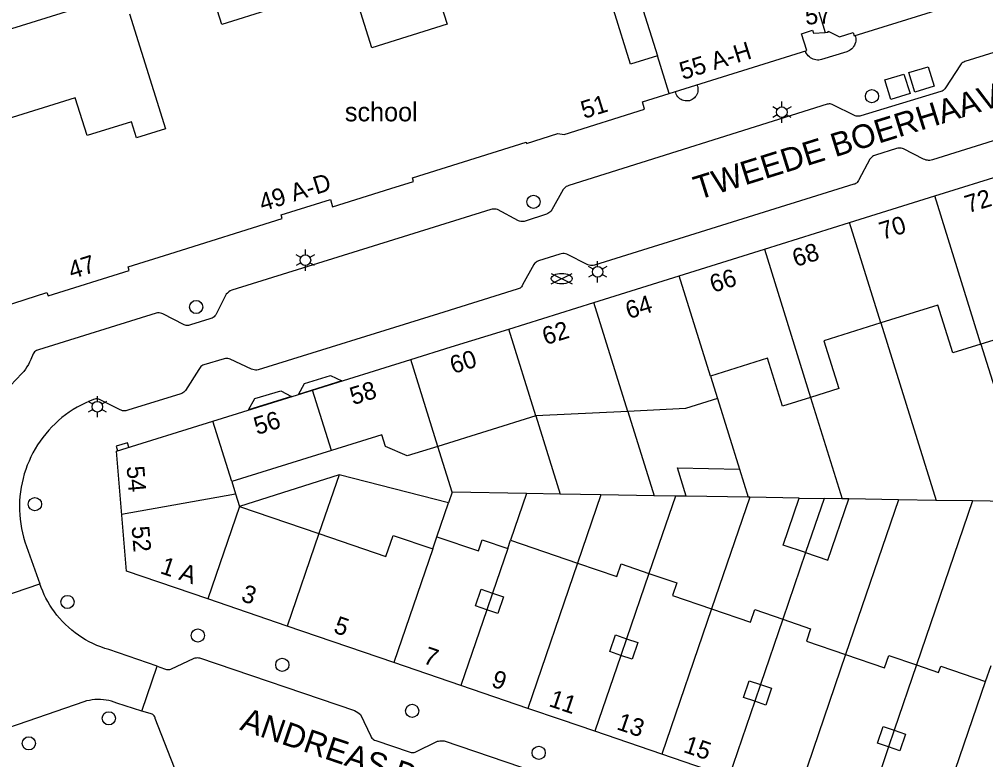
# Model space of a CAD drawing. Extents: x 122462 to 123306, y 485548 to 486417.
# Drawn here: x 122727.9 to 122810, y 485830.6 to 485893.5 of the extents above; entities that cross this region are included whole.
import ezdxf

# ---------------------------------------------------------------- set-up
doc = ezdxf.new("R2010")
doc.units = 0
for name, color, linetype in [('B-WE-IE-MEUBILAIR_WEGMEUBILAIR_VERKEERSBORD-S', 7, 'Continuous'), ('Level 1', 7, 'Continuous'), ('Level 10', 7, 'Continuous'), ('Level 11', 7, 'Continuous'), ('Level 17', 7, 'Continuous'), ('Level 19', 7, 'Continuous'), ('Level 2', 7, 'Continuous'), ('Level 4', 7, 'Continuous'), ('Level 40', 7, 'Continuous'), ('Level 42', 7, 'Continuous'), ('Level 50', 7, 'Continuous'), ('Level 52', 7, 'Continuous'), ('Level 53', 7, 'Continuous'), ('Level 62', 7, 'Continuous'), ('N-WE-AL-T25', 7, 'Continuous'), ('N-WE-GR-BOOM_DOORWORTELBARE RUIMTE-G', 7, 'Continuous')]:
    doc.layers.add(name, color=color, linetype=linetype)

msp = doc.modelspace()

# ---------------------------------------------------------------- linework, layer by layer
at = {"layer": 'Level 1'}
for p, q in [((122805.66, 485878.489), (122812.618, 485880.656)), ((122798.427, 485876.231), (122805.66, 485878.489)), ((122791.193, 485873.971), (122798.427, 485876.231)), ((122783.959, 485871.711), (122791.193, 485873.971)), ((122776.725, 485869.451), (122783.959, 485871.711)), ((122769.489, 485867.189), (122776.725, 485869.451)), ((122752.831, 485862.006), (122761.161, 485864.598)), ((122786.615, 485863.192), (122787.212, 485861.277)), ((122744.368, 485859.372), (122752.831, 485862.006)), ((122771.792, 485859.813), (122763.461, 485857.217)), ((122779.612, 485860.192), (122771.792, 485859.813)), ((122754.431, 485856.87), (122745.968, 485854.233)), ((122745.968, 485854.233), (122746.288, 485853.206)), ((122746.288, 485853.206), (122746.627, 485852.12)), ((122746.627, 485852.12), (122753.368, 485849.816)), ((122763.031, 485848.517), (122763.385, 485849.552)), ((122769.401, 485848.56), (122769.639, 485849.256)), ((122769.639, 485849.256), (122775.329, 485847.311)), ((122750.682, 485841.957), (122743.941, 485844.263)), ((122759.729, 485838.86), (122750.682, 485841.957)), ((122765.421, 485836.916), (122759.729, 485838.86)), ((122809.978, 485837.258), (122810.439, 485838.605)), ((122771.11, 485834.969), (122765.421, 485836.916)), ((122782.494, 485831.088), (122776.809, 485833.029)), ((122788.178, 485829.144), (122782.494, 485831.088))]:
    msp.add_line(p, q, dxfattribs=at)
for points in [[(122782.111, 485890.389), (122779.836, 485889.68), (122776.933, 485898.985), (122779.2, 485899.692), (122778.052, 485903.361), (122777.009, 485903.036)], [(122787.577, 485901.162), (122779.528, 485898.643), (122782.111, 485890.389)], [(122763.191, 485896.451), (122764.246, 485893.07), (122757.854, 485891.075), (122755.209, 485899.548)], [(122749.287, 485894.36), (122745.115, 485893.057), (122744.165, 485896.101)], [(122796.371, 485892.381), (122796.609, 485892.396), (122796.604, 485892.486), (122797.563, 485891.992), (122798.727, 485892.355), (122798.811, 485892.088), (122810.229, 485895.65)], [(122737.289, 485893.955), (122740.339, 485884.181), (122737.882, 485883.414), (122737.452, 485884.79), (122733.686, 485883.614), (122732.684, 485886.823), (122726.415, 485884.866), (122725.594, 485887.497), (122718.359, 485885.239), (122718.533, 485884.68), (122716.39, 485883.999), (122716.428, 485883.886), (122716.294, 485883.843)], [(122783.11, 485887.189), (122794.792, 485890.834), (122794.345, 485892.266), (122795.281, 485892.558), (122795.355, 485892.319), (122796.371, 485892.381)], [(122721.249, 485867.901), (122721.34, 485867.91), (122723.61, 485868.642), (122723.749, 485868.199), (122730.269, 485870.299), (122730.37, 485869.999), (122737.259, 485872.16), (122737.166, 485872.466), (122740.722, 485873.58), (122750.259, 485876.569), (122750.165, 485876.879), (122754.35, 485878.189), (122754.529, 485877.559), (122759.482, 485879.109), (122761.4, 485879.709), (122761.301, 485880.031), (122770.958, 485883.053), (122770.989, 485882.949), (122773.66, 485883.789), (122774.189, 485883.709), (122781.029, 485885.85), (122780.835, 485886.479), (122783.11, 485887.189)], [(122815.276, 485872.131), (122810.708, 485870.706), (122811.975, 485866.643), (122809.588, 485865.899)], [(122809.588, 485865.899), (122807.202, 485865.155), (122805.935, 485869.217), (122801.086, 485867.705)], [(122761.161, 485864.598), (122764.611, 485865.671), (122769.489, 485867.189)], [(122801.086, 485867.705), (122796.238, 485866.193), (122797.505, 485862.131), (122795.118, 485861.386)], [(122795.118, 485861.386), (122792.732, 485860.642), (122791.465, 485864.704), (122786.615, 485863.192)], [(122787.212, 485861.277), (122784.489, 485860.428), (122779.612, 485860.192)], [(122743.941, 485844.263), (122737.019, 485846.63), (122736.17, 485856.819), (122744.368, 485859.372)], [(122763.461, 485857.217), (122760.861, 485856.407), (122759.027, 485857.214), (122758.718, 485858.206), (122754.431, 485856.87)], [(122753.368, 485849.816), (122759.055, 485847.872), (122759.669, 485849.666), (122763.031, 485848.517)], [(122763.385, 485849.552), (122766.918, 485848.344), (122767.244, 485849.298), (122769.401, 485848.56)], [(122775.329, 485847.311), (122778.663, 485846.172), (122779.028, 485847.24), (122781.393, 485846.432)], [(122781.393, 485846.432), (122783.759, 485845.623), (122783.394, 485844.555), (122786.71, 485843.421)], [(122767.621, 485843.351), (122766.674, 485843.675), (122767.159, 485845.095), (122768.106, 485844.771)], [(122768.106, 485844.771), (122769.052, 485844.448), (122768.567, 485843.028), (122767.621, 485843.351)], [(122786.71, 485843.421), (122790.029, 485842.287), (122790.394, 485843.356), (122792.759, 485842.547)], [(122792.759, 485842.547), (122795.125, 485841.738), (122794.759, 485840.669), (122798.077, 485839.535)], [(122779.011, 485839.466), (122778.065, 485839.79), (122778.551, 485841.21), (122779.497, 485840.887)], [(122779.497, 485840.887), (122780.444, 485840.563), (122779.958, 485839.142), (122779.011, 485839.466)], [(122798.077, 485839.535), (122801.39, 485838.403), (122801.755, 485839.472), (122804.12, 485838.663)], [(122804.12, 485838.663), (122805.994, 485838.023), (122806.177, 485838.558), (122809.978, 485837.258)], [(122790.378, 485835.58), (122789.432, 485835.903), (122789.917, 485837.323), (122790.863, 485837)], [(122790.863, 485837), (122791.809, 485836.676), (122791.324, 485835.256), (122790.378, 485835.58)], [(122776.809, 485833.029), (122773.96, 485833.999), (122771.11, 485834.969)], [(122801.738, 485831.696), (122800.792, 485832.019), (122801.277, 485833.439), (122802.223, 485833.116)], [(122802.223, 485833.116), (122803.17, 485832.792), (122802.685, 485831.372), (122801.738, 485831.696)]]:
    msp.add_lwpolyline(points, dxfattribs=at)
at = {"layer": 'Level 10'}
for points in [[(122751.637, 485861.634), (122752.153, 485862.556), (122754.359, 485863.246), (122755.302, 485862.775), (122751.637, 485861.634)], [(122747.398, 485860.315), (122747.926, 485861.287), (122750.14, 485861.939), (122751.03, 485861.445), (122747.398, 485860.315)]]:
    msp.add_lwpolyline(points, dxfattribs=at)
at = {"layer": 'Level 11'}
for points in [[(122798.91, 485892.119), (122798.94, 485891.999), (122798.957, 485891.877), (122798.96, 485891.753), (122798.949, 485891.63), (122798.925, 485891.509), (122798.887, 485891.392), (122798.836, 485891.279), (122798.772, 485891.173), (122798.697, 485891.075), (122798.612, 485890.985), (122798.517, 485890.906), (122798.414, 485890.838), (122798.304, 485890.782), (122798.188, 485890.739), (122796.059, 485890.075), (122795.939, 485890.045), (122795.817, 485890.028), (122795.693, 485890.026), (122795.57, 485890.037), (122795.449, 485890.062), (122795.332, 485890.1), (122795.219, 485890.151), (122795.113, 485890.215), (122795.015, 485890.29), (122794.926, 485890.375), (122794.847, 485890.47), (122794.779, 485890.573), (122794.723, 485890.683), (122794.68, 485890.799)], [(122785.464, 485887.925), (122785.509, 485887.812), (122785.54, 485887.694), (122785.555, 485887.573), (122785.555, 485887.451), (122785.539, 485887.331), (122785.509, 485887.213), (122785.464, 485887.1), (122785.404, 485886.993), (122785.332, 485886.895), (122785.248, 485886.807), (122785.154, 485886.73), (122785.05, 485886.666), (122784.94, 485886.615), (122784.823, 485886.579), (122784.703, 485886.558), (122784.582, 485886.552), (122784.46, 485886.561), (122784.341, 485886.586), (122784.226, 485886.626), (122784.117, 485886.679), (122784.015, 485886.747), (122783.923, 485886.826), (122783.842, 485886.917), (122783.772, 485887.017), (122783.716, 485887.125), (122783.674, 485887.239), (122783.647, 485887.358)]]:
    msp.add_lwpolyline(points, dxfattribs=at)
at = {"layer": 'Level 17'}
for p, q in [((122726.438, 485844.434), (122729.679, 485845.54)), ((122738.321, 485834.728), (122739.631, 485838.555))]:
    msp.add_line(p, q, dxfattribs=at)
for points in [[(122825.381, 485895.245), (122808.209, 485889.895), (122808.123, 485889.862), (122808.041, 485889.817), (122807.967, 485889.762), (122807.9, 485889.698), (122807.842, 485889.626), (122806.575, 485887.656), (122806.516, 485887.577), (122806.447, 485887.507), (122806.369, 485887.448), (122806.283, 485887.4), (122806.191, 485887.365), (122799.392, 485885.284), (122799.293, 485885.265), (122799.192, 485885.257), (122799.092, 485885.261), (122798.992, 485885.277), (122798.895, 485885.304), (122796.955, 485886.254), (122796.873, 485886.281), (122796.788, 485886.297), (122796.702, 485886.302), (122796.616, 485886.295), (122796.532, 485886.277), (122774.587, 485879.372), (122774.478, 485879.332), (122774.375, 485879.277), (122774.28, 485879.208), (122774.196, 485879.128), (122774.123, 485879.037), (122773.136, 485877.296)], [(122827.346, 485888.392), (122805.468, 485881.555), (122805.362, 485881.528), (122805.253, 485881.513), (122805.143, 485881.51), (122805.034, 485881.519), (122804.926, 485881.54), (122804.822, 485881.572), (122804.721, 485881.616), (122803.006, 485882.477), (122802.912, 485882.512), (122802.814, 485882.535), (122802.714, 485882.547), (122802.614, 485882.546), (122802.514, 485882.535), (122802.416, 485882.511), (122800.644, 485881.961), (122800.549, 485881.927), (122800.458, 485881.882), (122800.373, 485881.827), (122800.295, 485881.763), (122800.224, 485881.691), (122800.162, 485881.611), (122799.223, 485879.869), (122799.189, 485879.788), (122799.142, 485879.712), (122799.085, 485879.644), (122799.019, 485879.586), (122798.945, 485879.538), (122798.864, 485879.502), (122798.779, 485879.478)], [(122798.779, 485879.478), (122776.782, 485872.606), (122776.668, 485872.582), (122776.551, 485872.573), (122776.435, 485872.579), (122776.32, 485872.6), (122776.209, 485872.636), (122774.429, 485873.553), (122774.311, 485873.58), (122774.19, 485873.594), (122774.068, 485873.594), (122773.947, 485873.58), (122773.829, 485873.553), (122772.001, 485872.967), (122771.911, 485872.927), (122771.828, 485872.876), (122771.752, 485872.813), (122771.686, 485872.741), (122771.63, 485872.661), (122770.665, 485870.931), (122770.631, 485870.852), (122770.584, 485870.779), (122770.526, 485870.716), (122770.458, 485870.662), (122770.382, 485870.621), (122770.301, 485870.592), (122770.216, 485870.577), (122763.535, 485868.492), (122748.215, 485863.71), (122748.099, 485863.7), (122747.982, 485863.702), (122747.866, 485863.716), (122747.753, 485863.742), (122747.642, 485863.779), (122745.831, 485864.618), (122745.734, 485864.65), (122745.633, 485864.672), (122745.531, 485864.682), (122745.429, 485864.682), (122745.327, 485864.67), (122743.603, 485864.161), (122743.509, 485864.121), (122743.422, 485864.069), (122743.344, 485864.004), (122743.276, 485863.928), (122743.22, 485863.843), (122743.177, 485863.751), (122742.037, 485861.977), (122741.972, 485861.897), (122741.898, 485861.826), (122741.815, 485861.764), (122741.726, 485861.712), (122741.631, 485861.672), (122737.136, 485860.305), (122737.05, 485860.266), (122736.959, 485860.241), (122736.865, 485860.23), (122736.77, 485860.233), (122736.677, 485860.252), (122736.588, 485860.284), (122736.505, 485860.329), (122734.741, 485861.196), (122734.644, 485861.229), (122734.542, 485861.248), (122734.439, 485861.25), (122734.337, 485861.237), (122734.238, 485861.209), (122733.877, 485861.064), (122733.522, 485860.904), (122733.173, 485860.731), (122732.832, 485860.544), (122732.498, 485860.343), (122732.173, 485860.129), (122731.857, 485859.902), (122731.549, 485859.663), (122731.252, 485859.412), (122730.965, 485859.149), (122730.688, 485858.875), (122730.423, 485858.59), (122730.17, 485858.295), (122729.928, 485857.99), (122729.699, 485857.675), (122729.482, 485857.352), (122729.279, 485857.02), (122729.089, 485856.68), (122728.912, 485856.333), (122728.75, 485855.979), (122728.602, 485855.619), (122728.468, 485855.253), (122728.349, 485854.883), (122728.245, 485854.507), (122728.156, 485854.129), (122728.082, 485853.746), (122728.024, 485853.361), (122727.981, 485852.974), (122727.953, 485852.586), (122727.941, 485852.197), (122727.945, 485851.808), (122727.964, 485851.419), (122727.998, 485851.031), (122728.048, 485850.645)], [(122773.136, 485877.296), (122773.068, 485877.205), (122772.989, 485877.124), (122772.899, 485877.054), (122772.802, 485876.996), (122772.697, 485876.952), (122770.889, 485876.355), (122770.794, 485876.331), (122770.697, 485876.319), (122770.599, 485876.319), (122770.502, 485876.331), (122770.407, 485876.354), (122770.315, 485876.389), (122768.537, 485877.342), (122768.422, 485877.363), (122768.305, 485877.373), (122768.188, 485877.372), (122768.072, 485877.359), (122767.957, 485877.335), (122760.987, 485875.165), (122745.977, 485870.493), (122745.844, 485870.424), (122745.719, 485870.342), (122745.603, 485870.247), (122745.498, 485870.141), (122744.603, 485868.387), (122744.542, 485868.304), (122744.469, 485868.23), (122744.387, 485868.168), (122744.296, 485868.118), (122744.2, 485868.081), (122744.099, 485868.059), (122742.459, 485867.541), (122742.374, 485867.511), (122742.287, 485867.492), (122742.197, 485867.486), (122742.108, 485867.492), (122742.02, 485867.51), (122741.935, 485867.54), (122740.128, 485868.471), (122740.019, 485868.511), (122739.906, 485868.537), (122739.79, 485868.551), (122739.674, 485868.551), (122739.559, 485868.538), (122729.559, 485865.433), (122729.466, 485865.401), (122729.378, 485865.358), (122729.296, 485865.304), (122729.221, 485865.24), (122729.154, 485865.168), (122729.097, 485865.088), (122728.901, 485864.595), (122728.805, 485864.38), (122728.696, 485864.171), (122728.576, 485863.968), (122728.444, 485863.773), (122728.301, 485863.586), (122728.147, 485863.408), (122724.252, 485859.341)], [(122728.048, 485850.645), (122728.114, 485850.261), (122728.194, 485849.881), (122728.29, 485849.503), (122728.401, 485849.13), (122729.679, 485845.54)], [(122739.631, 485838.555), (122735.52, 485839.962), (122735.178, 485840.069), (122734.841, 485840.189), (122734.509, 485840.323), (122734.183, 485840.471), (122733.863, 485840.632), (122733.55, 485840.806), (122733.244, 485840.992), (122732.946, 485841.191), (122732.657, 485841.402), (122732.376, 485841.625), (122732.105, 485841.859), (122731.843, 485842.104), (122731.592, 485842.359), (122731.352, 485842.624), (122731.122, 485842.899), (122730.904, 485843.183), (122730.698, 485843.476), (122730.518, 485843.752), (122730.349, 485844.036), (122730.191, 485844.325), (122730.045, 485844.621), (122729.911, 485844.923), (122729.789, 485845.229), (122729.679, 485845.54)], [(122739.631, 485838.555), (122740.259, 485838.34), (122740.342, 485838.304), (122740.429, 485838.281), (122740.518, 485838.27), (122740.608, 485838.272), (122740.697, 485838.286), (122740.783, 485838.313), (122742.787, 485839.233), (122742.873, 485839.261), (122742.961, 485839.279), (122743.051, 485839.285), (122743.141, 485839.279), (122743.23, 485839.262), (122756.394, 485834.783), (122756.53, 485834.716), (122756.659, 485834.637), (122756.78, 485834.546), (122756.892, 485834.444), (122757.764, 485832.611), (122757.814, 485832.529), (122757.873, 485832.453), (122757.942, 485832.385), (122758.017, 485832.326), (122758.1, 485832.277), (122758.188, 485832.238), (122761.037, 485831.283), (122761.118, 485831.251), (122761.203, 485831.23), (122761.29, 485831.221), (122761.378, 485831.224), (122761.464, 485831.24), (122761.547, 485831.267), (122763.426, 485832.175), (122763.537, 485832.202), (122763.65, 485832.219), (122763.764, 485832.225), (122763.878, 485832.221), (122763.991, 485832.206), (122771.807, 485829.543)], [(122738.321, 485834.728), (122736.214, 485835.427), (122735.991, 485835.51), (122735.763, 485835.579), (122735.532, 485835.636), (122735.298, 485835.679), (122735.062, 485835.709), (122734.825, 485835.725), (122734.587, 485835.727), (122734.349, 485835.716), (122734.113, 485835.691), (122733.878, 485835.653), (122733.646, 485835.601), (122733.417, 485835.536), (122728.649, 485833.886), (122723.355, 485832.067)], [(122741.35, 485829.279), (122739.467, 485834.113), (122739.451, 485834.191), (122739.422, 485834.265), (122739.381, 485834.333), (122739.329, 485834.394), (122739.269, 485834.445), (122739.2, 485834.485), (122739.126, 485834.514), (122739.048, 485834.53), (122738.321, 485834.728)]]:
    msp.add_lwpolyline(points, dxfattribs=at)
at = {"layer": 'Level 19'}
for p, q in [((122801.086, 485867.705), (122805.785, 485852.636)), ((122809.588, 485865.899), (122813.766, 485852.502)), ((122795.118, 485861.386), (122797.805, 485852.769)), ((122787.212, 485861.277), (122789.075, 485855.299)), ((122771.792, 485859.813), (122773.864, 485853.17)), ((122779.612, 485860.192), (122781.843, 485853.036)), ((122764.674, 485853.323), (122763.461, 485857.217)), ((122755.074, 485854.807), (122746.627, 485852.12)), ((122755.074, 485854.807), (122753.368, 485849.816)), ((122764.367, 485852.425), (122755.074, 485854.807)), ((122764.674, 485853.323), (122764.367, 485852.425)), ((122770.993, 485853.217), (122764.674, 485853.323)), ((122770.993, 485853.217), (122769.639, 485849.256)), ((122773.864, 485853.17), (122770.993, 485853.217)), ((122777.312, 485853.112), (122773.864, 485853.17)), ((122777.312, 485853.112), (122775.329, 485847.311)), ((122781.843, 485853.036), (122777.312, 485853.112)), ((122763.385, 485849.552), (122764.367, 485852.425)), ((122783.641, 485853.006), (122781.393, 485846.432)), ((122783.641, 485853.006), (122781.843, 485853.036)), ((122784.558, 485852.991), (122783.641, 485853.006)), ((122789.951, 485852.9), (122786.71, 485843.421)), ((122789.951, 485852.9), (122789.822, 485852.903)), ((122794.16, 485852.83), (122789.951, 485852.9)), ((122802.574, 485852.69), (122798.077, 485839.535)), ((122802.574, 485852.69), (122798.363, 485852.76)), ((122805.785, 485852.636), (122802.574, 485852.69)), ((122808.879, 485852.584), (122804.12, 485838.663)), ((122808.879, 485852.584), (122805.785, 485852.636)), ((122813.766, 485852.502), (122808.879, 485852.584)), ((122794.69, 485848.198), (122792.759, 485842.547)), ((122768.106, 485844.771), (122767.621, 485843.351)), ((122779.497, 485840.887), (122779.011, 485839.466)), ((122790.863, 485837), (122790.378, 485835.58)), ((122802.223, 485833.116), (122801.738, 485831.696))]:
    msp.add_line(p, q, dxfattribs=at)
at = {"layer": 'Level 2'}
for p, q in [((122789.075, 485855.299), (122789.822, 485852.903)), ((122789.822, 485852.903), (122784.558, 485852.991)), ((122794.16, 485852.83), (122796.261, 485852.795)), ((122796.261, 485852.795), (122794.69, 485848.198)), ((122797.805, 485852.769), (122796.261, 485852.795)), ((122798.363, 485852.76), (122797.805, 485852.769))]:
    msp.add_line(p, q, dxfattribs=at)
for points in [[(122745.957, 485905.45), (122747.928, 485899.135), (122718.763, 485890.034), (122716.792, 485896.349)], [(122784.558, 485852.991), (122783.811, 485855.387), (122789.075, 485855.299)], [(122794.69, 485848.198), (122792.798, 485848.844), (122794.16, 485852.83)], [(122794.69, 485848.198), (122796.583, 485847.551), (122798.363, 485852.76)]]:
    msp.add_lwpolyline(points, dxfattribs=at)
at = {"layer": 'Level 4'}
for p, q in [((122783.11, 485887.189), (122782.111, 485890.389)), ((122809.588, 485865.899), (122805.66, 485878.489)), ((122801.086, 485867.705), (122798.427, 485876.231)), ((122791.193, 485873.971), (122795.118, 485861.386)), ((122786.615, 485863.192), (122783.959, 485871.711)), ((122779.612, 485860.192), (122776.725, 485869.451)), ((122771.792, 485859.813), (122769.489, 485867.189)), ((122763.461, 485857.217), (122761.161, 485864.598)), ((122754.431, 485856.87), (122752.831, 485862.006)), ((122745.968, 485854.233), (122744.368, 485859.372)), ((122746.627, 485852.12), (122743.941, 485844.263)), ((122753.368, 485849.816), (122750.682, 485841.957)), ((122763.031, 485848.517), (122759.729, 485838.86)), ((122769.401, 485848.56), (122768.106, 485844.771)), ((122775.329, 485847.311), (122771.11, 485834.969)), ((122781.393, 485846.432), (122779.497, 485840.887)), ((122767.621, 485843.351), (122765.421, 485836.916)), ((122786.71, 485843.421), (122782.494, 485831.088)), ((122792.759, 485842.547), (122790.863, 485837)), ((122779.011, 485839.466), (122776.809, 485833.029)), ((122798.077, 485839.535), (122793.86, 485827.199)), ((122804.12, 485838.663), (122802.223, 485833.116)), ((122805.214, 485823.321), (122809.978, 485837.258)), ((122790.378, 485835.58), (122788.178, 485829.144)), ((122801.738, 485831.696), (122799.538, 485825.261))]:
    msp.add_line(p, q, dxfattribs=at)
at = {"layer": 'Level 40'}
msp.add_lwpolyline([(122737.225, 485857.149), (122737.105, 485857.533), (122736.149, 485857.235), (122736.269, 485856.851)], dxfattribs=at)
at = {"layer": 'Level 42'}
for points in [[(122803.972, 485887.313), (122803.456, 485888.965), (122805.091, 485889.465), (122805.607, 485887.814), (122803.972, 485887.313)], [(122801.926, 485886.687), (122801.41, 485888.338), (122803.045, 485888.839), (122803.561, 485887.187), (122801.926, 485886.687)]]:
    msp.add_lwpolyline(points, dxfattribs=at)
at = {"layer": 'Level 50'}
for p, q in [((122792.291, 485885.825), (122791.901, 485886.05)), ((122792.681, 485886.05), (122792.681, 485886.5)), ((122793.46, 485886.05), (122793.07, 485885.825)), ((122792.291, 485885.375), (122791.901, 485885.15)), ((122792.681, 485884.7), (122792.681, 485885.15)), ((122793.46, 485885.15), (122793.07, 485885.375)), ((122752.219, 485873.486), (122752.219, 485873.936)), ((122751.829, 485873.261), (122751.439, 485873.486)), ((122751.829, 485872.811), (122751.439, 485872.586)), ((122752.998, 485873.486), (122752.608, 485873.261)), ((122752.998, 485872.586), (122752.608, 485872.811)), ((122777.038, 485872.495), (122777.038, 485872.945)), ((122752.219, 485872.136), (122752.219, 485872.586)), ((122776.648, 485872.27), (122776.258, 485872.495)), ((122777.817, 485872.495), (122777.427, 485872.27)), ((122776.648, 485871.82), (122776.258, 485871.595)), ((122777.038, 485871.145), (122777.038, 485871.595)), ((122777.817, 485871.595), (122777.427, 485871.82)), ((122734.554, 485861.04), (122734.554, 485861.49)), ((122734.164, 485860.815), (122733.774, 485861.04)), ((122735.333, 485861.04), (122734.943, 485860.815)), ((122734.164, 485860.365), (122733.774, 485860.14)), ((122734.554, 485859.69), (122734.554, 485860.14)), ((122735.333, 485860.14), (122734.943, 485860.365))]:
    msp.add_line(p, q, dxfattribs=at)
for centre in [(122792.681, 485885.6), (122752.219, 485873.036), (122777.038, 485872.045), (122734.554, 485860.59)]:
    msp.add_circle(centre, 0.45, dxfattribs=at)
at = {"layer": 'Level 52'}
for p, q in [((122773.097, 485871.025), (122774.878, 485871.915)), ((122773.097, 485871.915), (122774.878, 485871.025))]:
    msp.add_line(p, q, dxfattribs=at)
msp.add_ellipse((122773.987, 485871.468), major_axis=(0.89, 0), ratio=0.5, dxfattribs=at)
at = {"layer": 'Level 53'}
for centre in [(122800.329, 485886.956), (122771.587, 485877.99), (122742.943, 485869.058), (122729.253, 485852.318), (122732.012, 485844.011), (122743.08, 485841.159), (122750.26, 485838.669), (122761.28, 485834.759), (122735.53, 485834.129), (122728.74, 485831.999), (122772.03, 485831.199)]:
    msp.add_circle(centre, 0.56, dxfattribs=at)
at = {"layer": 'N-WE-AL-T25'}
for p, q in [((122793.084, 485902.885), (122796.371, 485892.381)), ((122736.617, 485851.479), (122746.288, 485853.206)), ((122746.288, 485853.206), (122746.289, 485853.206))]:
    msp.add_line(p, q, dxfattribs=at)

# ---------------------------------------------------------------- texts
at = {"layer": 'B-WE-IE-MEUBILAIR_WEGMEUBILAIR_VERKEERSBORD-S'}
for s, rotation, p in [('57', 3.32515, (122794.69, 485893.034)), ('55 A-H', 17.32514, (122784.267, 485888.335)), ('51', 17.38073, (122775.887, 485885.026)), ('49 A-D', 17.3813, (122748.571, 485877.166)), ('72', 17.28553, (122808.487, 485877.015)), ('70', 17.33732, (122801.225, 485874.747)), ('68', 17.35579, (122793.85, 485872.445)), ('47', 17.41604, (122732.379, 485871.415)), ('66', 17.35579, (122786.834, 485870.254)), ('64', 17.35579, (122779.68, 485868.018)), ('62', 17.35579, (122772.613, 485865.81)), ('60', 17.29097, (122764.767, 485863.364)), ('58', 17.29097, (122756.266, 485860.718)), ('56', 17.29097, (122748.111, 485858.18)), ('54', 274.74243, (122737.035, 485855.511)), ('52', 274.73527, (122737.459, 485850.413)), ('1 A', 341.11758, (122739.805, 485846.472)), ('3', 341.11861, (122746.677, 485844.12)), ('5', 341.11861, (122754.533, 485841.433)), ('7', 341.11861, (122762.135, 485838.833)), ('9', 341.11861, (122767.925, 485836.854)), ('11', 341.20341, (122772.814, 485835.185)), ('13', 341.20341, (122778.567, 485833.221)), ('15', 341.20341, (122784.239, 485831.281))]:
    msp.add_text(s, height=1.5, rotation=rotation, dxfattribs=at).set_placement(p)
at = {"layer": 'Level 62'}
msp.add_text('school', height=1.6, dxfattribs=at).set_placement((122755.572, 485884.825))
at = {"layer": 'N-WE-GR-BOOM_DOORWORTELBARE RUIMTE-G'}
for s, rotation, p in [('TWEEDE BOERHAAVESTRAAT', 17.33147, (122785.568, 485878.141)), ('ANDREAS BONNSTRAAT', 341.13203, (122746.572, 485833.189))]:
    msp.add_text(s, height=2, rotation=rotation, dxfattribs=at).set_placement(p)

doc.saveas('drawing.dxf')
